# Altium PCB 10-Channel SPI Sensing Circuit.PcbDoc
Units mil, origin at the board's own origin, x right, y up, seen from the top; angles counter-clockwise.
Board outline 1023.62 x 1141.73 mil, 4 copper layers (Top Layer, GroundPlane, PowerPlane, Bottom Layer), stack 70.17 mil thick; 32 components, 41 nets, 191 pads, 54 vias.
Unrouted connection lines stored in the file: 1.
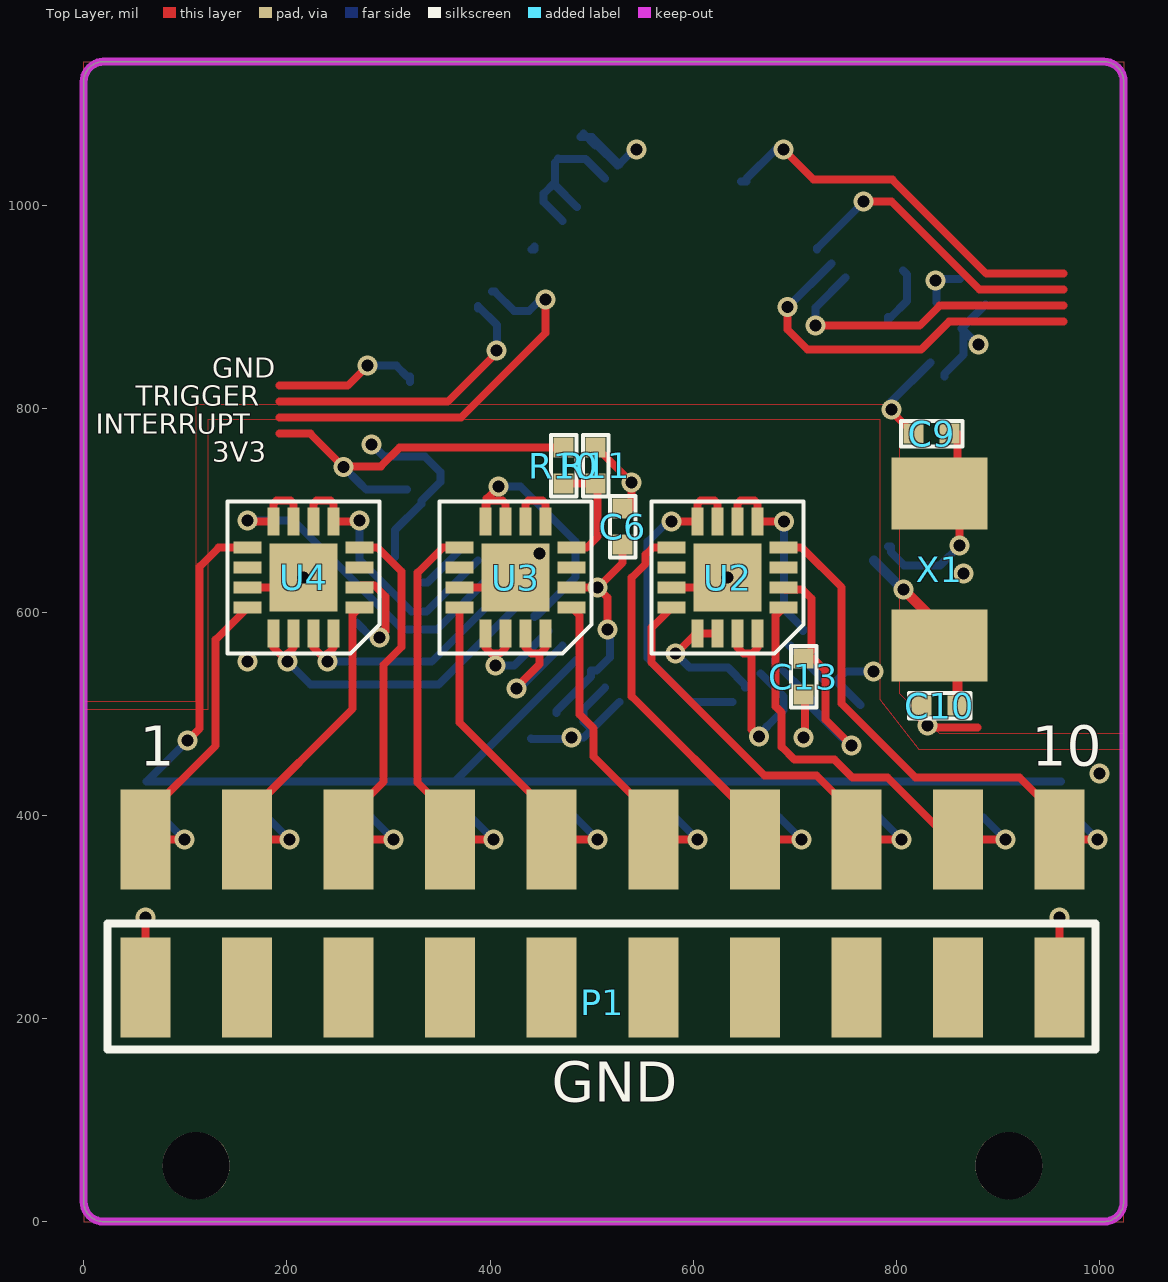
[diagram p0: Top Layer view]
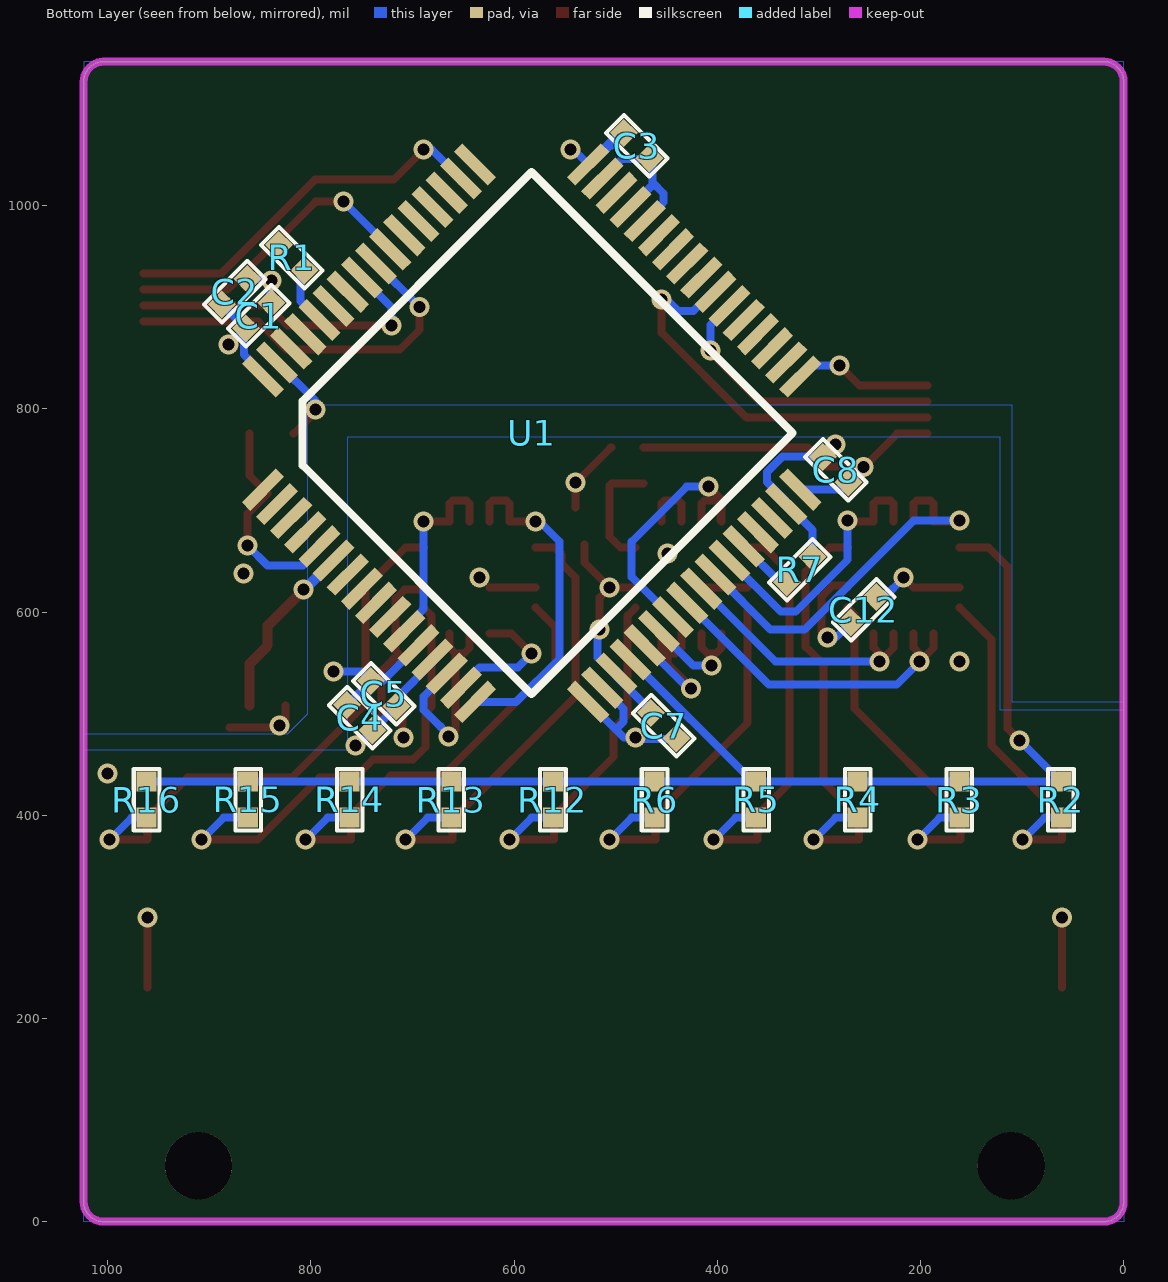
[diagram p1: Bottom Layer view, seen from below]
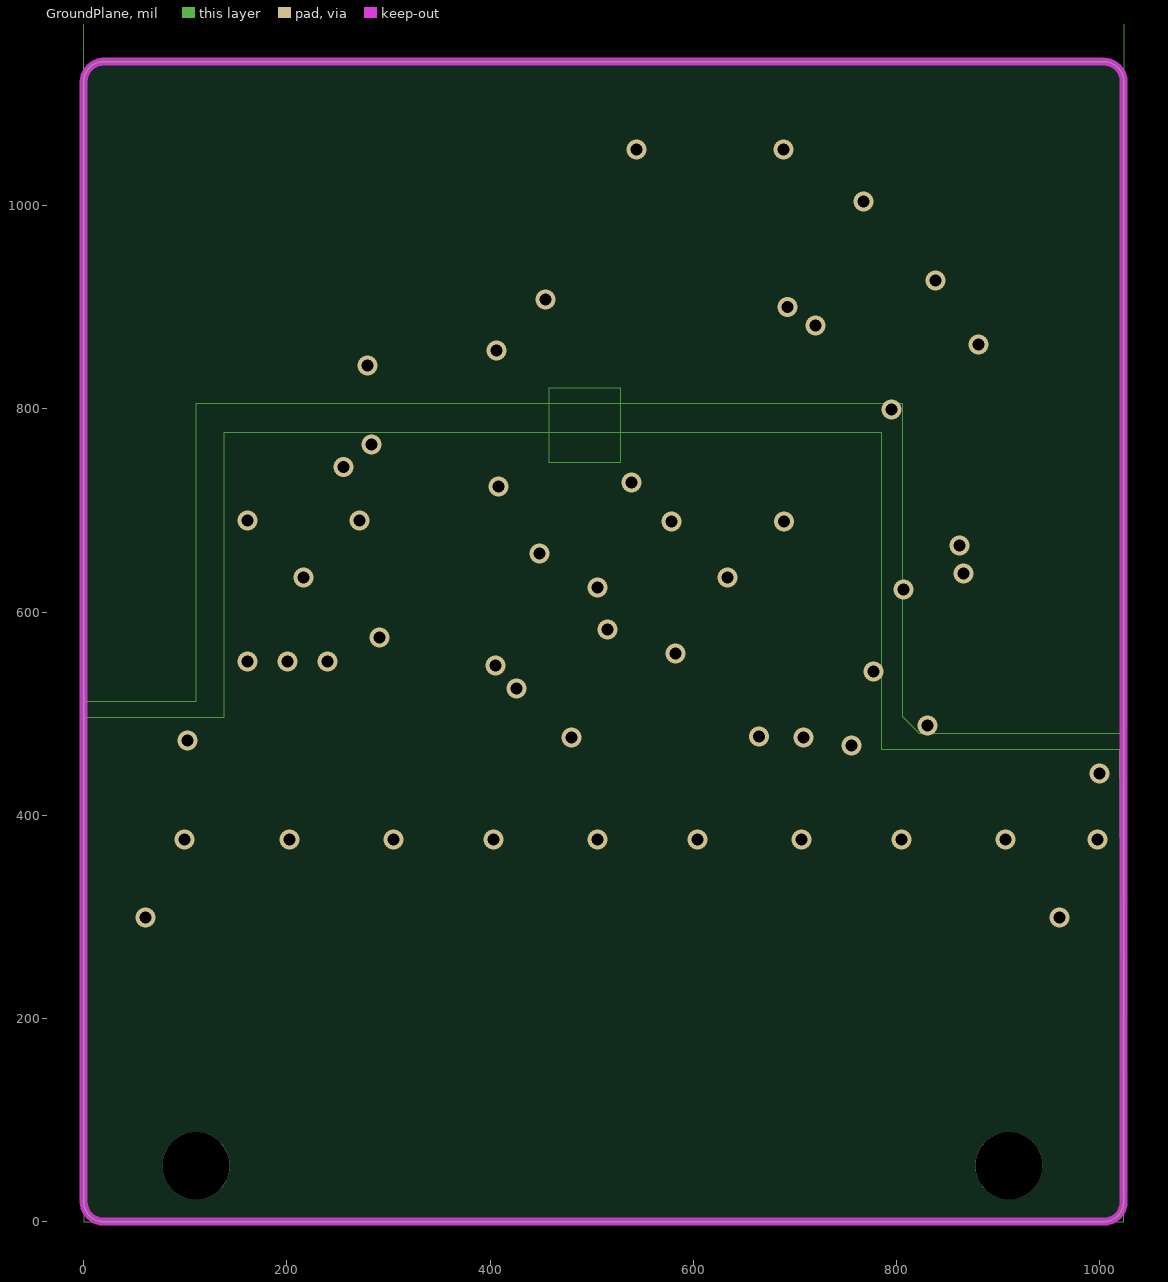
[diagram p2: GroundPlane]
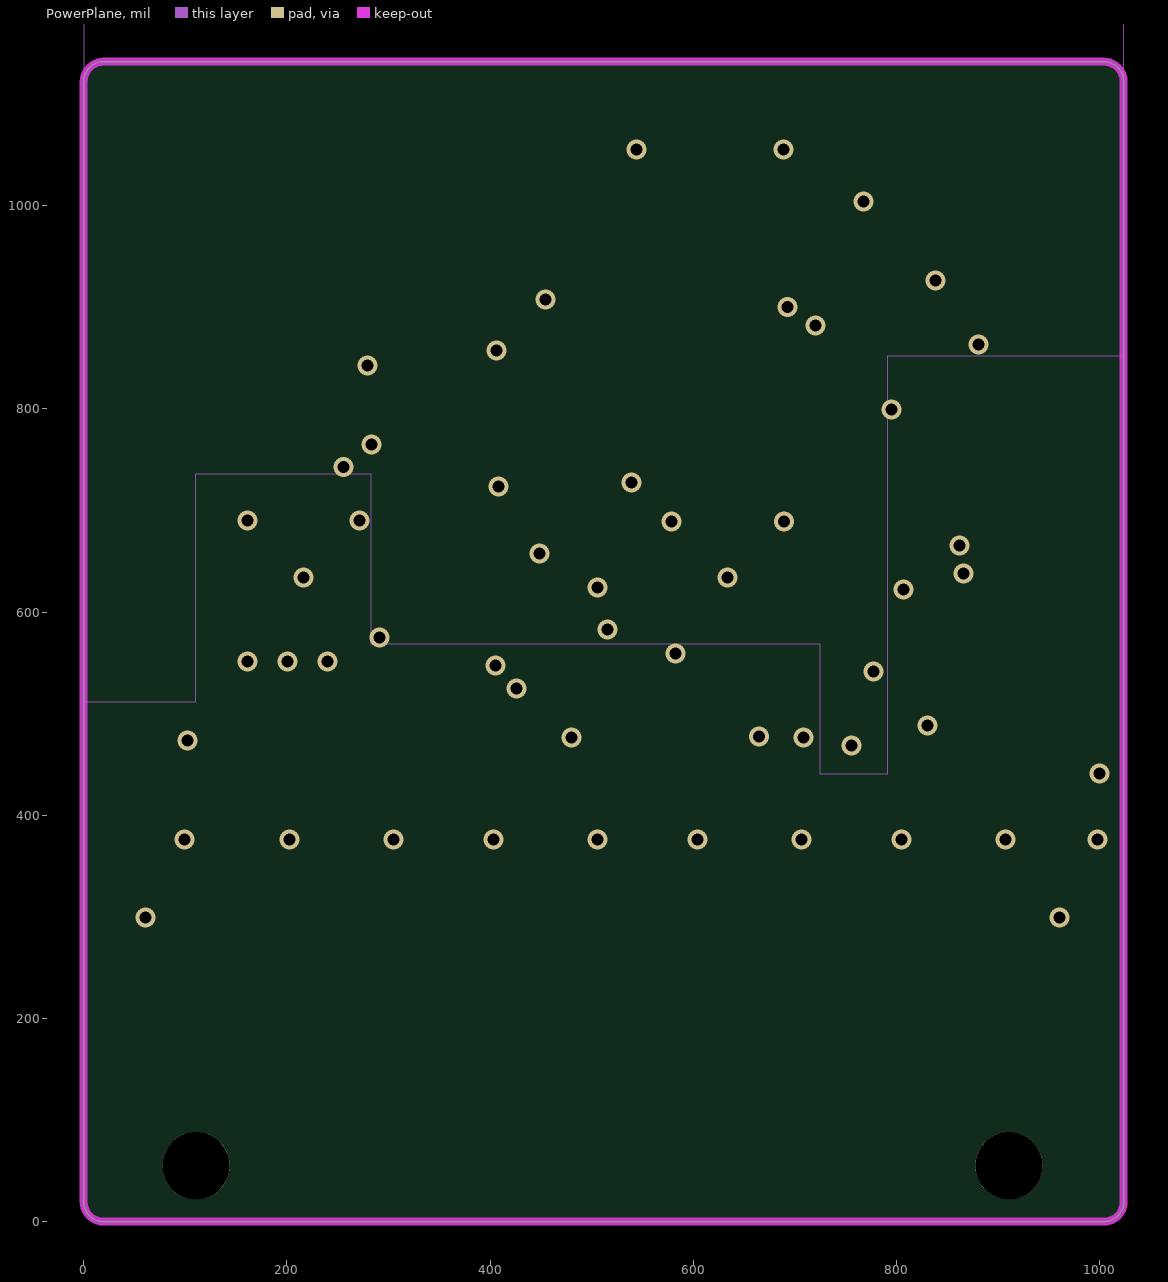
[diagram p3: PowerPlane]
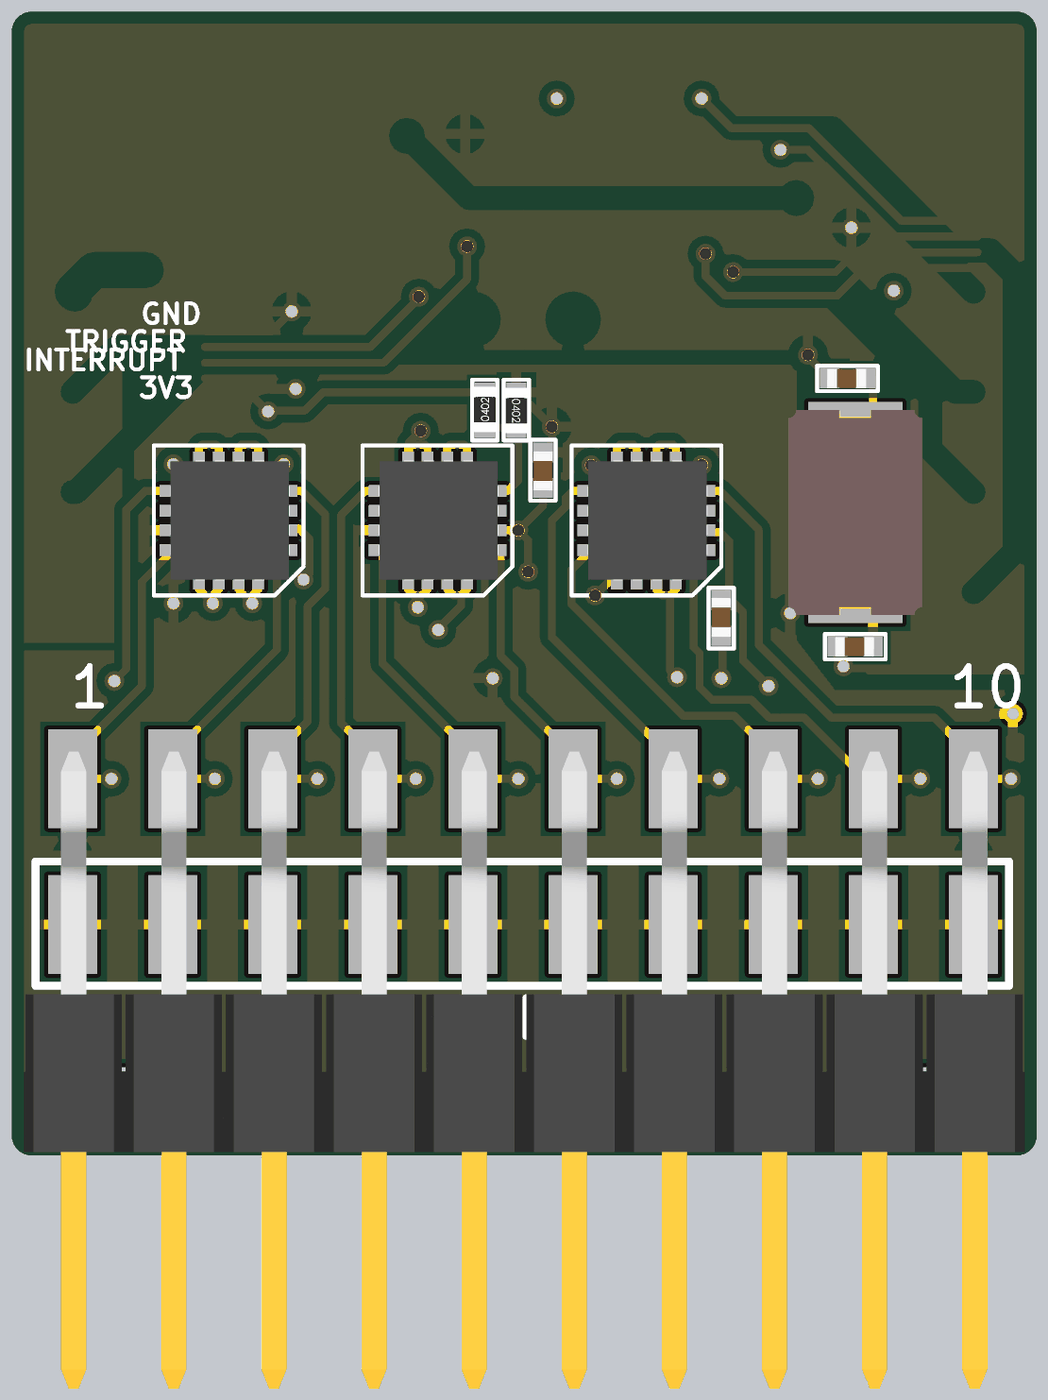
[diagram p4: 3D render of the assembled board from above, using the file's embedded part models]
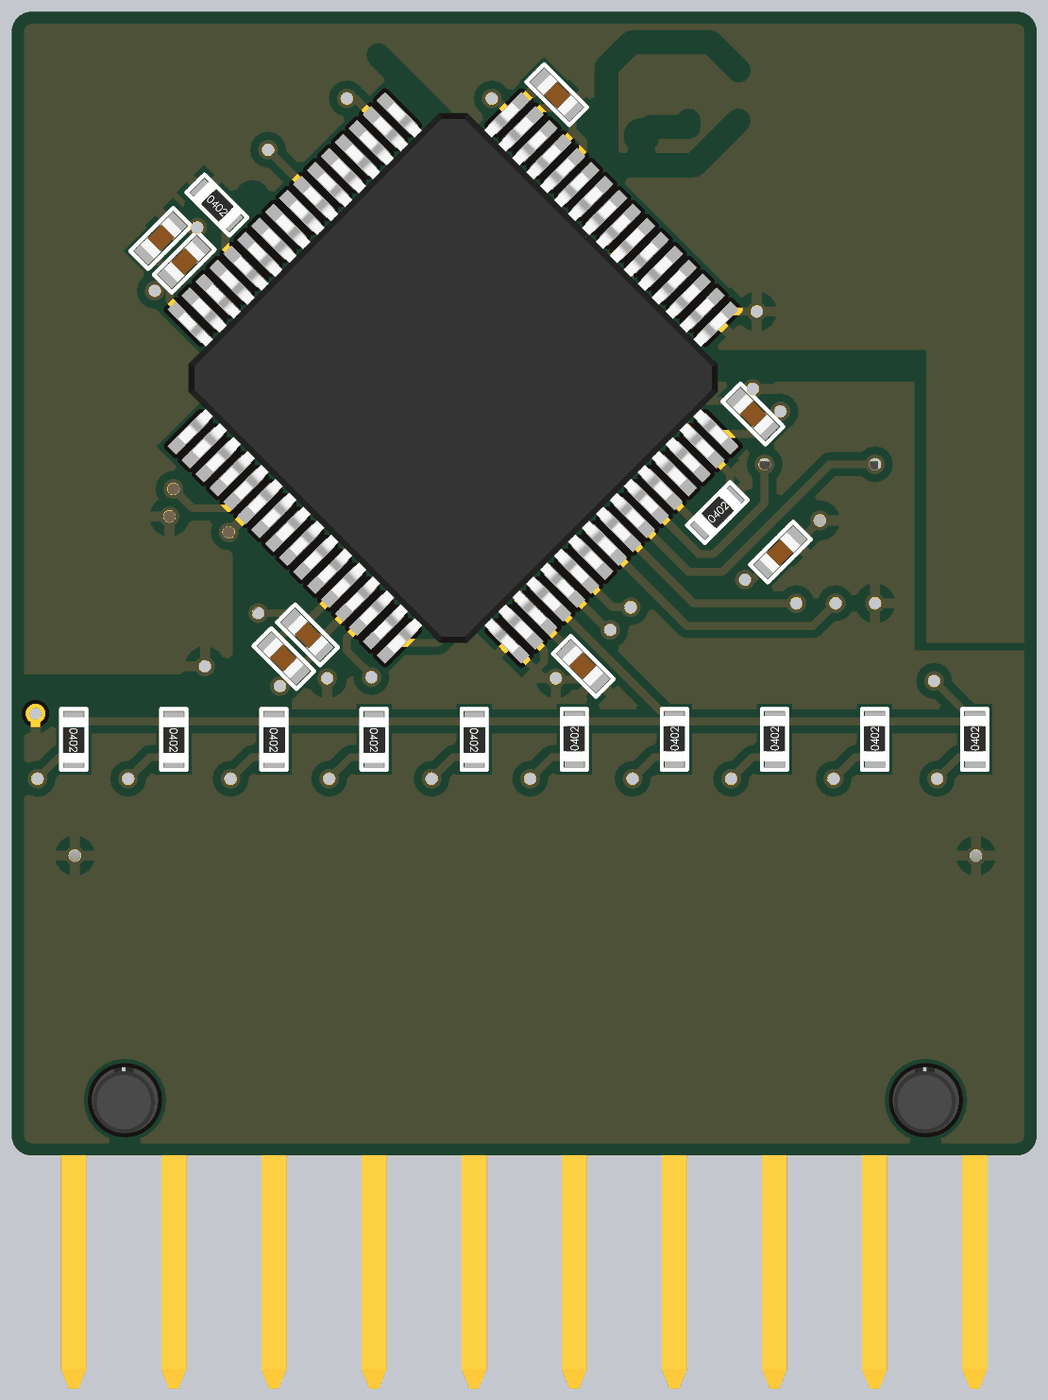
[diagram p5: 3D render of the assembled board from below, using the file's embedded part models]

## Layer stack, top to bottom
Top Solder: solder mask 0.4, Solder Resist, Dk 3.5
Top Layer: signal copper 1.4
Dielectric1: prepreg 12.6, FR-4, Dk 4.8
GroundPlane: signal copper 1.4
Dielectric3: core 39.37, FR-4, Dk 4.8
PowerPlane: signal copper 1.4
Dielectric2: prepreg 12.6, FR-4, Dk 4.8
Bottom Layer: signal copper 1.4
Bottom Solder: solder mask 0.4, Solder Resist, Dk 3.5

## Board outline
0,19.68 0,1122.05 cw(c19.68,1122.05) 19.68,1141.73 1003.94,1141.73 cw(c1003.94,1122.05) 1023.62,1122.05 1023.62,19.68 cw(c1003.94,19.68) 1003.94,0 19.68,0 cw(c19.68,19.68)

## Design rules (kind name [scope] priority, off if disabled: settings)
Clearance [All] p1: gap=7.87
MinimumSolderMaskSliver [All] p1 off: minsoldermaskwidth=10
PolygonConnect [All] p1: connectstyle=Relief reliefconductorwidth=10 reliefentries=4 polygonreliefangle="90 Angle" airgapwidth=10
RoutingVias [All] p1: holewidth=28 width=50 viastyle="Through Hole" minholewidth=11.81 minwidth=19.68 maxholewidth=28 maxwidth=50
SilkToSolderMaskClearance SilkscreenOverComponentPads [IsPad] p1 off: minsilkscreentomaskgap=10 clearancetoexposedcopper=TRUE
SolderMaskExpansion [All] p1: expansion=4
Width [All] p1: maxlimit=78.74 minlimit=7.87 preferedwidth=7.87
28 further rules are at their usual default settings.

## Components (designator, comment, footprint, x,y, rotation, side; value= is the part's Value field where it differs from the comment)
C1 "100nF" "0402 CAP" 851.38,891.73 r135 bottom
C2 "4.7uF" "0402 CAP" 875,915.35 r135 bottom
C3 "100nF" "0402 CAP" 479.33,1059.06 r225 bottom
C4 "10nF" "0402 CAP" 751.97,496.06 r45 bottom
C5 "1uF" "0402 CAP" 728.35,519.69 r225 bottom
C6 "100nF" "0402 Cap" 530.51,684.06 r270 top
C7 "100nF" "0402 CAP" 452.76,488.19 r45 bottom
C8 "100nF" "0402 CAP" 283.46,740.16 r225 bottom
C9 "36pF" "0402 Cap" 834.65,775.59 r180 top
C10 "36pF" "0402 Cap" 842.52,507.87 r180 top
C12 "100nF" "0402 Cap" 255.91,602.36 r315 bottom
C13 "100nF" "0402 Cap" 708.66,536.42 r90 top
P1 "HDR2X10 SMD Right Angle" "HDR2X10 SMD RIGHT" 960.63,230.31 r180 top
R1 "10k" "0402 RES" 818.9,948.82 r225 bottom
R2 "510k 1%" "0402 RES" 61.81,415.35 r90 bottom
R3 "510k 1%" "0402 RES" 161.81,415.35 r90 bottom
R4 "510k 1%" "0402 RES" 261.81,415.35 r90 bottom
R5 "510k 1%" "0402 RES" 361.81,415.35 r90 bottom
R6 "510k 1%" "0402 RES" 461.81,415.35 r90 bottom
R7 "10k" "0402 RES" 318.9,641.73 r135 bottom
R10 "100k" "0402 Res" 472.44,744.09 r90 top
R11 "100k" "0402 Res" 503.94,744.09 r270 top
R12 "510k 1%" "0402 Res" 561.81,415.35 r270 bottom
R13 "510k 1%" "0402 Res" 661.81,415.35 r270 bottom
R14 "510k 1%" "0402 Res" 761.81,415.35 r270 bottom
R15 "510k 1%" "0402 Res" 861.81,415.35 r270 bottom
R16 "510k 1%" "0402 Res" 961.81,415.35 r270 bottom
U1 "STM32F105R8" STM32F105R8 847.24,720.47 r135 bottom
U2 "TSV634IQ4T" QFN-16 633.86,633.86 r180 top
U3 "TSV634IQ4T" QFN-16 425.2,633.86 r180 top
U4 "TSV634IQ4T" QFN-16 216.54,633.86 r180 top
X1 "CRYSTAL 25MHZ 18PF" "CRYSTAL 24MHZ 18PF SMD" 842.52,641.73 r270 top

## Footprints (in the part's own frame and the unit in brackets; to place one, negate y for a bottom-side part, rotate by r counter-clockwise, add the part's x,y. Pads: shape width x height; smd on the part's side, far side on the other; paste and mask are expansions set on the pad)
"0402 CAP" [mm] "Source: PADS"
  rect 0.5x0.5 smd mask+0: 1(-0.45,0) 2(0.45,0)
  silkscreen extent -0.77,-0.32 0.77,0.32, body extent -0.48,-0.25 0.52,0.25, height 0.5
"0402 Cap" [mm] "Source: PADS"
  rect 0.5x0.5 smd mask+0: 1(-0.45,0) 2(0.45,0)
  silkscreen extent -0.77,-0.32 0.77,0.32, body extent -0.48,-0.25 0.52,0.25, height 0.5
"0402 RES" [mm] "Source: PADS"
  rect 0.5x0.5 smd mask+0: 1(-0.45,0) 2(0.45,0)
  silkscreen extent -0.77,-0.32 0.77,0.32, body extent -0.56,-0.27 0.59,0.28, height 0.41
"0402 Res" [mm] "Source: PADS"
  rect 0.5x0.5 smd mask+0: 1(-0.45,0) 2(0.45,0)
  silkscreen extent -0.77,-0.32 0.77,0.32, body extent -0.56,-0.27 0.59,0.28, height 0.41
"CRYSTAL 24MHZ 18PF SMD" [mm] "445C25D24M00000"
  rect 1.8x2.4 smd: 0(1.9,0) 1(-1.9,0)
  body extent -2.6,-1.7 2.6,1.7, height 1.3
"HDR2X10 SMD RIGHT" [mm]
  rect 1.25x2.5 smd: 1(0,0) 2(2.54,0) 3(5.08,0) 4(7.62,0) 5(10.16,0) 6(12.7,0) 7(15.24,0) 8(17.78,0) 9(20.32,0) 10(22.86,0) 11(0,-3.7) 12(2.54,-3.7) 13(5.08,-3.7) 14(7.62,-3.7) 15(10.16,-3.7) 16(12.7,-3.7) 17(15.24,-3.7) 18(17.78,-3.7) 19(20.32,-3.7) 20(22.86,-3.7)
  round 1.68 hole 1.68 unplated: ""(1.27,4.45) ""(21.59,4.45)
  body extent -1.3,-4.39 24.1,11.77, height 5.04
QFN-16 [mm]
  rect 0.7x0.3 smd: 1(-1.4,0.75) 2(-1.4,0.25) 3(-1.4,-0.25) 4(-1.4,-0.75) 9(1.4,-0.75) 10(1.4,-0.25) 11(1.4,0.25) 12(1.4,0.75)
  rect 0.3x0.7 smd: 5(-0.75,-1.4) 6(-0.25,-1.4) 7(0.25,-1.4) 8(0.75,-1.4) 13(0.75,1.4) 14(0.25,1.4) 15(-0.25,1.4) 16(-0.75,1.4)
  rect 1.7x1.7 smd: 17(0,0)
  silkscreen extent -1.9,-1.9 1.9,1.9, body extent -1.55,-1.52 1.49,1.52, height 0.9
STM32F105R8 [mm] "STM32F10x 10mm x 10mm package"
  rect 1.2x0.3 smd: 1(0,0) 2(0,-0.5) 3(0,-1) 4(0,-1.5) 5(0,-2) 6(0,-2.5) 7(0,-3) 8(0,-3.5) 9(0,-4) 10(0,-4.5) 11(0,-5) 12(0,-5.5) 13(0,-6) 14(0,-6.5) 15(0,-7) 16(0,-7.5) 33(11.5,-7.5) 34(11.5,-7) 35(11.5,-6.5) 36(11.5,-6) 37(11.5,-5.5) 38(11.5,-5) 39(11.5,-4.5) 40(11.5,-4) 41(11.5,-3.5) 42(11.5,-3) 43(11.5,-2.5) 44(11.5,-2) 45(11.5,-1.5) 46(11.5,-1) 47(11.5,-0.5) 48(11.5,0)
  rect 0.3x1.2 smd: 17(2,-9.5) 18(2.5,-9.5) 19(3,-9.5) 20(3.5,-9.5) 21(4,-9.5) 22(4.5,-9.5) 23(5,-9.5) 24(5.5,-9.5) 25(6,-9.5) 26(6.5,-9.5) 27(7,-9.5) 28(7.5,-9.5) 29(8,-9.5) 30(8.5,-9.5) 31(9,-9.5) 32(9.5,-9.5) 49(9.5,2) 50(9,2) 51(8.5,2) 52(8,2) 53(7.5,2) 54(7,2) 55(6.5,2) 56(6,2) 57(5.5,2) 58(5,2) 59(4.5,2) 60(4,2) 61(3.5,2) 62(3,2) 63(2.5,2) 64(2,2)
  silkscreen extent 1.13,-8.36 10.36,0.87, body extent -0.25,-9.75 11.75,2.25, height 1.6

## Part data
C1 C3 C6 C7 C8 C12 C13: library part "Cap 0402 100nF 10%", "Capacitor"
C2: library part "Cap 0402 4.7uF 10%", "Capacitor"
C4: library part "Cap 0402 10nF 10%", "Capacitor"
C5: library part "Cap 0402 1uF 5%", "Capacitor"
C9 C10: library part "Cap 36pF 0402", "Capacitor"
P1: library part "Header 2x10 SMD R/A 2.54mm", "Header"
R1 R7: library part "Res 0402 10k 5%", "Resistor"
R2 R3 R4 R5 R6 R12 R13 R14 R15 R16: library part "Res 0402 510k 1%", "Resistor"
R10 R11: library part "Res 0402 100k 5%", "Resistor"
U1: "Microcontroller"
U2 U3 U4: library part "Quad Opamp TSV634IQ4T", "Quad Opamp"
X1: library part "CRYSTAL 25MHZ 18PF SMD", "445C25D24M00000"

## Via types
v1: diameter 19.68, hole 11.81, Top Layer to Bottom Layer, tented both sides, 53 vias
v2: diameter 19.68, hole 11.81, Top Layer to Bottom Layer, 1 vias

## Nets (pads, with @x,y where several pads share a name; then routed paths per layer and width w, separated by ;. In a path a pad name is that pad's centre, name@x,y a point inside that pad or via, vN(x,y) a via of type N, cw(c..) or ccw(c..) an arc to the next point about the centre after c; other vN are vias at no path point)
ADC_CH_0: U1.26 U4.7 U4.8 | length 389.5
  Top Layer w7.87: v1(161.42,689.96) v1@161.42,692.91 ; v1@165.35,688.98 U4.8 187.01,706.69 189.96,709.65 203.74,709.65 206.69,706.69 U4.7
  Bottom Layer w7.87: v1(161.42,689.96) 206.8,689.96 314.08,582.68 347.54,582.68 U1.26
ADC_CH_1: U1.24 U4.13 U4.14 | length 327
  Top Layer w7.87: U4.13 187.01,564.96 v1(200.79,551.18) ; v1@200.79,559.06 206.69,564.96 U4.14
  Bottom Layer w7.87: v1(200.79,551.18) 223.42,528.54 349.09,528.54 U1.24
ADC_CH_2: U1.25 U4.15 U4.16 | length 258
  Top Layer w7.87: U4.15 226.38,564.96 v1(240.16,551.18) ; v1@240.16,559.06 246.06,564.96 U4.16
  Bottom Layer w7.87: v1(240.16,551.18) 342.5,551.18 U1.25@413.37,622.06
ADC_CH_3: U1.27 U4.5 U4.6 | length 276.4
  Top Layer w7.87: U4.6 226.38,706.69 229.33,709.65 243.11,709.65 246.06,706.69 U4.5 v1@263.78,688.98 ; v1@267.72,688.98 268.7,689.96 v1(271.65,689.96)
  Bottom Layer w7.87: v1(271.65,689.96) 271.65,651.55 322.81,600.39 337.42,600.39 U1.27
ADC_CH_4: U1.23 U3.7 U3.8 | length 288.1
  Top Layer w7.87: v1(408.46,723.43) 396.65,711.61 396.65,689.96 U3.8 395.67,706.69 398.62,709.65 412.4,709.65 415.35,706.69 U3.7
  Bottom Layer w7.87: v1(408.46,723.43) 430.12,723.43 484.25,669.29 484.25,634.48 446.37,596.59 443.58,596.59 U1.23
ADC_CH_5: U1.22 U3.13 U3.14 | length 126.1
  Top Layer w7.87: U3.13 395.67,564.96 401.57,559.06 409.45,559.06 415.35,564.96 U3.14 ; v1(405.51,547.24) v1@405.51,555.12
  Bottom Layer w7.87: v1(405.51,547.24) 423.47,547.24 U1.22
ADC_CH_6: U1.21 U3.15 U3.16 | length 161.3
  Top Layer w7.87: v1(425.88,524.61) 425.2,525.29 448.82,548.92 448.82,559.06 ; U3.15 435.04,564.96 440.94,559.06 448.82,559.06 ; U3.16 454.72,564.96 448.82,559.06
  Bottom Layer w7.87: v1(425.88,524.61) 428.67,524.61 U1.21 U1.21@471.42,565.97
ADC_CH_7: U1.16 U2.7 U2.8 | length 334
  Top Layer w7.87: v1(578.74,688.98) 582.68,692.91 586.61,688.98 U2.8 604.33,706.69 607.28,709.65 621.06,709.65 624.02,706.69 U2.7
  Bottom Layer w7.87: v1(578.74,688.98) 574.8,688.98 555.12,669.29 555.12,554.6 598.04,511.68 U1.16
ADC_CH_8: U1.15 U2.13 U2.14 | length 134.7
  Top Layer w7.87: v1(582.68,559.06) 602.36,578.74 U2.13 U2.14
  Bottom Layer w7.87: v1(582.68,559.06) 596.38,545.36 634.01,545.36 650.98,528.38 650.98,525.6 U1.15
ADC_CH_9: U1.14 U2.15 U2.16 | length 218.6
  Top Layer w7.87: U2.15 643.7,564.96 649.61,559.06 657.48,559.06 ; U2.16 663.39,564.96 657.48,559.06 ; v1(664.45,477.42) 657.48,484.38 657.48,559.06
  Bottom Layer w7.87: v1(664.45,477.42) 664.45,479.45 672.2,487.2 672.32,487.09 688.98,503.74 688.98,516.84 U1.14
ADC_CH_10: U1.11 U2.5 U2.6 | length 191.1
  Top Layer w7.87: U2.6 643.7,706.69 646.65,709.65 660.43,709.65 663.39,706.69 U2.5 v1@681.1,688.98
  Bottom Layer w7.87: v1(689.28,689.28) 689.28,602.83 708.05,584.06 U1.11
BOOT0: R1.2 U1.60 | length 59.8
  Bottom Layer w7.87: U1.60 791.57,890.29 794.35,890.29 810.34,906.28 810.34,932.32 R1.2
DAC_OUT_1: R2.2 R3.2 R4.2 R5.2 R6.2 R12.1 R13.1 R14.1 R15.1 R16.1 U1.20 U4.9 | length 1355.4
  Top Layer w7.87: v1(102.36,473.62) 114.17,485.43 114.17,644.69 132.87,663.39 U4.9
  Bottom Layer w7.87: v1(102.36,473.62) R2.2 R3.2 R4.2 R5.2 ; U1.20 364.97,433.07 R6.2 R12.1 R13.1 R14.1 R15.1 R16.1
GND: C1.2 C2.2 C3.2 C4.2 C5.1 C6.1 C7.1 C8.1 C9.2 C10.2 C12.1 C13.1 P1.1 P1.2 P1.3 P1.4 P1.5 P1.6 P1.7 P1.8 P1.9 P1.10 R1.1 R7.2 R11.1 U1.12 U1.17 U1.18 U1.31 U1.33 U1.44 U1.45 U1.47 U1.63 U2.11 U2.17 U3.11 U3.17 U4.11 U4.17 | length 1438.9
  Top Layer w7.87: P1.10 v1(60.63,299.21) ; U4.11 206.69,624.02 v1(216.54,633.86) ; 192.91,822.83 259.84,822.83 v1(279.53,842.52) ; U3.11 415.35,624.02 U3.17 ; R11.1 504.89,761.81 v1(539.37,727.33) C6.1@539.37,702.76 ; U2.11 U2.17@624.02,624.02 ; C13.1 709.72,517.64 v1@709.72,483.3 ; v1(795.28,799.21) 795.28,797.24 C9.2 ; C10.2 824.8,494.09 v1(830.71,488.19) 832.68,486.22 879.92,486.22 ; P1.1 v1(960.63,299.21)
  Bottom Layer w7.87: v1(216.54,633.86) 235.5,614.89 C12.1 ; v1(279.53,842.52) 307.61,842.52 U1.33 321.09,831.83 U1.33@321.09,826.26 ; v1(283.46,765.21) C8.1 295.99,753.16 335.73,753.16 351,737.89 351,728.11 332.23,709.34 U1.31 306.37,680.7 R7.2 ; C7.1 440.9,474.99 v1@477.49,474.99 ; C3.2@463.85,1042.59 463.85,1022.91 ; C3.2 466.8,1045.85 494.03,1045.85 U1.47 ; U1.44 452.76,1003.61 452.76,1011.81 463.85,1022.91 ; U1.45 463.85,1020.35 463.85,1022.91 ; U1.18 492.13,504.55 492.13,492.46 500,484.58 ; U1.17 500,484.58 ; U1.12@695.55,567.36 U1.12 729.28,532.21 C5.1 ; C4.2 C5.1 ; v1(777.56,541.34) 750,541.34 C5.1 ; v1(795.28,799.21) 795.28,807.7 U1.63 ; C1.2@839.57,904.98 v1@839.57,927.17 ; v1@840.28,927.88 C2.2 ; v1@477.49,474.99 478.92,474.99 v1(480.31,476.38) ; v1@477.49,474.99 478.88,476.38 v1(480.31,476.38) ; v1(480.31,476.38) 491.79,476.38 500,484.58
  other v1: 708.66,476.38 161.42,551.18 633.86,633.86 866.14,637.8 448.82,657.48 838.58,926.18
  other v2: 1000,440.94
INTERRUPT: U1.39 | length 394.2
  Top Layer w7.87: 192.91,791.34 371.17,791.34 454.72,874.88 v1(454.72,907.48)
  Bottom Layer w7.87: U1.39 404.61,915.34 423.38,896.57 438.49,896.57 449.4,907.48 v1(454.72,907.48)
NetR7_1: R7.1 U1.28 | length 57.3
  Bottom Layer w7.87: R7.1 338.39,629.2 U1.28
NetR10_1: R10.1 R11.2 U3.4 | length 114.6
  Top Layer w7.87: R10.1 R11.2 505.91,724.41 505.91,674.21 495.08,663.39 U3.4
NetU3_5: U3.5 U3.6 | length 57.6
  Top Layer w7.87: U3.6 435.04,706.69 437.99,709.65 451.77,709.65 454.72,706.69 U3.5
OSC_IN: C9.1 U1.5 X1.1 | length 215.4
  Top Layer w7.87: C9.1@860.24,775.59 860.24,734.25 X1.1 862.2,696.85 v1(862.2,665.35)
  Bottom Layer w7.87: U1.5 794.35,664.79 794.35,659.23 807.55,646.02 842.87,646.02 v1(862.2,665.35)
OSC_OUT: C10.1 U1.6 X1.0 | length 177.6
  Top Layer w9.84: v1(807.09,622.05) 842.52,586.61 X1.0 860.24,549.21 C10.1
  Bottom Layer w9.84: U1.6 806.48,622.05 v1(807.09,622.05)
RESET: U1.7
SENSE_1: P1.20 R2.1 U4.12 | length 355.4
  Top Layer w7.87: v1(99.41,375.98) P1.20 60.63,399.21 129.92,468.5 129.92,572.83 U4.12
  Bottom Layer w7.87: R2.1 77.76,397.64 v1(99.41,375.98)
SENSE_2: P1.19 R3.1 U4.1 | length 366.4
  Top Layer w7.87: v1(202.76,375.98) P1.19 160.63,400.79 264.76,504.92 264.76,597.44 U4.1
  Bottom Layer w7.87: R3.1 181.1,397.64 v1(202.76,375.98)
SENSE_3: P1.18 R4.1 U4.4 | length 433.4
  Top Layer w7.87: U4.4 289.37,663.39 312.99,639.76 312.99,565.83 295.28,548.12 295.28,433.07 260.63,398.43 P1.18 v1(305.12,375.98)
  Bottom Layer w7.87: R4.1 283.46,397.64 v1(305.12,375.98)
SENSE_4: P1.17 R5.1 U3.9 | length 421.2
  Top Layer w7.87: U3.9 353.35,663.39 328.74,638.78 328.74,432.09 360.63,400.2 P1.17 v1(403.54,375.98)
  Bottom Layer w7.87: R5.1 381.89,397.64 v1(403.54,375.98)
SENSE_5: P1.16 R6.1 U3.12 | length 364.2
  Top Layer w7.87: U3.12 370.08,491.14 460.63,400.59 P1.16 v1(505.91,375.98)
  Bottom Layer w7.87: R6.1 484.25,397.64 v1(505.91,375.98)
SENSE_6: P1.15 R12.2 U3.1 | length 356.8
  Top Layer w7.87: U3.1 488.19,596.46 488.19,499.12 501.97,485.34 501.97,457.68 560.63,399.02 P1.15 v1(604.33,375.98)
  Bottom Layer w7.87: R12.2 582.68,397.64 v1(604.33,375.98)
SENSE_7: P1.14 R13.2 U2.9 | length 464.8
  Top Layer w7.87: U2.9 560.04,663.39 553.15,656.5 553.15,647.64 539.37,633.86 539.37,517.1 660.63,395.84 P1.14 v1(706.69,375.98)
  Bottom Layer w7.87: R13.2 685.04,397.64 v1(706.69,375.98)
SENSE_8: P1.13 R14.2 U2.12 | length 446.7
  Top Layer w7.87: U2.12 559.06,584.65 559.06,550.2 670.28,438.98 721.46,438.98 760.63,399.8 P1.13 v1(805.12,375.98)
  Bottom Layer w7.87: R14.2 783.46,397.64 v1(805.12,375.98)
SENSE_9: P1.12 R15.2 U2.1 | length 455.6
  Top Layer w7.87: U2.1 681.1,596.46 681.1,507.13 687.01,501.23 687.01,467.41 699.69,454.72 739.06,454.72 756.78,437.01 791.34,437.01 852.36,375.98 P1.12 v1(907.48,375.98)
  Bottom Layer w7.87: R15.2 885.83,397.64 v1(907.48,375.98)
SENSE_10: P1.11 R16.2 U2.4 | length 554.5
  Top Layer w7.87: U2.4@689.96,662.4 U2.4 707.07,663.39 746.06,624.39 746.06,509.84 818.9,437.01 921.26,437.01 960.63,397.64 P1.11 v1(998.03,375.98)
  Bottom Layer w7.87: R16.2 976.38,397.64 v1(998.03,375.98)
SPI_CLK: U1.55 | length 298.5
  Top Layer w7.87: v1(767.72,1003.94) 795.28,1003.94 881.89,917.32 964.57,917.32
  Bottom Layer w7.87: U1.55 721.97,958.19 v1(767.72,1003.94)
SPI_MISO: U1.56 | length 374.3
  Top Layer w7.87: v1(692.91,900.21) 692.91,877.95 712.6,858.27 824.19,858.27 851.74,885.83 964.57,885.83
  Bottom Layer w7.87: v1(692.91,900.21) U1.56
SPI_MOSI: U1.57 | length 311.8
  Top Layer w7.87: v1(720.47,881.89) 822.83,881.89 842.52,901.57 964.57,901.57
  Bottom Layer w7.87: v1(720.47,881.89) 720.47,899.93 U1.57
SPI_NSS: U1.50 | length 382.9
  Top Layer w7.87: v1(688.98,1055.12) 718.5,1025.59 795.89,1025.59 888.41,933.07 964.57,933.07
  Bottom Layer w7.87: U1.50@646.8,1023.92 652.37,1023.92 U1.50 680.79,1055.12 v1(688.98,1055.12)
SWCLK: U1.49
SWDIO: U1.46
TRIGGER: U1.38 | length 295.8
  Top Layer w7.87: 192.91,807.09 358.27,807.09 408.46,857.28 v1(406.5,857.28) v1@406.5,860.21
  Bottom Layer w7.87: U1.38@387.9,898.82 U1.38 406.67,882.65 406.67,857.46 v1(406.5,857.28)
USART1_RX: U1.43
USART1_TX: U1.42 | length 5.6
  Bottom Layer w7.87: U1.42@440.8,957.1 U1.42 U1.42@443.58,959.89
VCC: C1.1 C2.1 C3.1 C4.1 C5.2 C6.2 C7.2 C8.2 C12.2 C13.2 R10.2 U1.13 U1.19 U1.32 U1.48 U1.64 U2.2 U3.2 U4.2 | length 1265.2
  Top Layer w7.87: 192.91,775.59 222.98,775.59 v1(255.91,742.66) 256.8,743.56 292.43,743.56 310.69,761.81 R10.2 ; U4.2 273.62,625.98 286.39,625.98 297.24,615.13 297.24,580.71 v1(291.34,574.8) ; U3.2 v1(505.91,624.02) ; v1(515.75,582.68) 515.75,614.17 v1(505.91,624.02) ; C6.2 530.51,648.62 v1(505.91,624.02) ; U2.2 690.95,622.05 707.65,622.05 716.54,613.16 716.54,562.01 C13.2 718.5,554.13 730.31,542.32 730.31,494.09 v1(755.91,468.5)
  Bottom Layer w7.87: v1(255.91,742.66) C8.2 278.09,720.47 U1.32 ; C12.2 283.47,574.8 v1(291.34,574.8) ; C7.2 465.28,502.76 499.26,536.74 499.26,542.3 504.83,542.3 518.03,555.51 518.03,580.4 v1(515.75,582.68) ; U1.48 500.07,1067.65 488.91,1067.65 492.13,1070.87 503.6,1059.39 505.54,1059.39 525.56,1039.37 541.31,1055.12 v1(544.28,1055.12) ; U1.13 680.21,550.66 715.82,515.05 C5.2 C4.1 754.47,468.5 v1(755.91,468.5) ; U1.64 847.24,834.61 866.01,853.38 C1.1@866.01,877.1 ; v1(880.91,863.19) 879.92,863.19 C1.1@866.01,877.1 ; C2.1 C1.1 C1.1@866.01,877.1
pads on no net: P1. U1.1 U1.2 U1.3 U1.4 U1.8 U1.9 U1.10 U1.29 U1.30 U1.34 U1.35 U1.36 U1.37 U1.40 U1.41 U1.51 U1.52 U1.53 U1.54 U1.58 U1.59 U1.61 U1.62 U2.3 U2.10 U3.3 U3.10 U4.3 U4.10

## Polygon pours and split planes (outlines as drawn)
GND on Top Layer "TopAnalogGND" (solid, remove dead copper, shelved, pour order 1012): 0,0 1023.62,0 1023.62,464.57 822.27,464.57 784.21,513.94 784.21,789.53 122.05,789.53 122.05,503.94 0,503.94
GND on Top Layer "DigitalGNDTop" (solid, remove dead copper, shelved, pour order 1004): 1023.62,1141.73 1023.62,480.31 842.52,480.31 803.15,519.68 803.15,804.13 110.24,804.13 110.24,511.81 0,511.81 0,1141.73
GND on Bottom Layer "Top Layer-No Net" (solid, remove dead copper, shelved, pour order 1001): 0,0 1023.62,0 1023.62,464.57 763.78,464.57 763.78,772.64 122.05,772.64 122.05,503.94 0,503.94
GND on Bottom Layer "DigitalGNDBottom" (solid, remove dead copper, shelved, pour order 1010): 1023.62,1141.73 1023.62,480.31 822.83,480.31 803.15,500 803.15,804.13 110.24,804.13 110.24,511.81 0,511.81 0,1141.73
GND on GroundPlane "GNDConnector" (solid, shelved, pour order 1008): 457.68,820.37 457.68,747.54 528.54,747.54 528.54,820.37
GND on GroundPlane "Top Layer-No Net" (solid, remove dead copper, shelved, pour order 1002): 0,0 1023.62,0 1019.47,464.57 785.43,464.57 785.43,776.57 137.8,776.57 137.8,496.06 0,496.06
GND on GroundPlane "DigitalGNDInternal" (solid, remove dead copper, shelved, pour order 1006): 1023.62,1220.47 1023.62,480.31 822.83,480.31 806.1,497.05 806.1,805.12 110.24,805.12 110.24,511.81 0,511.81 0,1220.47
VCC on PowerPlane "Top Layer-No Net" (solid, remove dead copper, shelved, pour order 1003): 0,511.81 110.24,511.81 110.24,736.22 282.48,736.22 282.48,568.9 724.41,568.9 724.41,440.94 791.34,440.94 791.34,852.36 1023.62,852.36 1023.62,1220.47 0,1220.47

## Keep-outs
Keep-Out Layer:
  the board outline again, w7.87

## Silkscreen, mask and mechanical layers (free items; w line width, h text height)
Top Overlay:
  lines w7.87: 23.62,169.29 23.62,293.31 996.06,293.31 996.06,169.29 23.62,169.29
  text "StretchSense" at 299.21,1275.59 h106.3
  text "GND" at 126.6,830.71 h19.68
  text "TRIGGER" at 51.17,803.15 h19.68
  text "INTERRUPT" at 11.81,775.59 h19.68
  text "3V3" at 126.6,748.03 h19.68
  text "1" at 55.12,448.82 h39.37
  text "10" at 933.07,448.82 h39.37
  text "GND" at 460.63,118.11 h39.37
